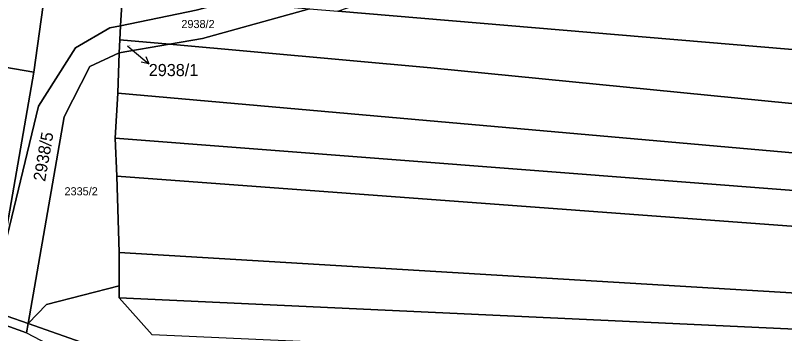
# Model space of a CAD drawing. Extents: x -596024 to -594475, y -1163820 to -1161957.
# Drawn here: x -595937.3 to -595829.3, y -1163270.2 to -1163225.5 of the extents above; entities that cross this region are included whole.
import ezdxf

# ---------------------------------------------------------------- set-up
doc = ezdxf.new("R2010")
doc.units = 0
for name, color, linetype in [('Level 1', 7, 'Continuous'), ('Level 3', 7, 'Continuous'), ('Level 4', 7, 'Continuous'), ('Level 57', 7, 'Continuous'), ('Level 60', 7, 'Continuous')]:
    doc.layers.add(name, color=color, linetype=linetype)

msp = doc.modelspace()

# ---------------------------------------------------------------- linework, layer by layer
at = {"layer": 'Level 1'}
for points in [[(-595675.06, -1163215.07), (-595742.82, -1163230.33), (-595776.16, -1163236.05), (-595801.34, -1163238.84), (-595828.3, -1163237.91), (-595878.95, -1163232.89), (-595915.65, -1163229.59)], [(-595932.62, -1163218.69), (-595934.67, -1163233.53)], [(-595922.49, -1163226.99), (-595922.2, -1163222.4)], [(-595922.49, -1163226.99), (-595911.9, -1163224.8), (-595907.4, -1163223.65)], [(-595895.98, -1163224.61), (-595911, -1163228.8), (-595915.65, -1163229.59)], [(-595891.99, -1163224.95), (-595828.78, -1163230.26), (-595802.13, -1163230.39), (-595778.15, -1163228.18)], [(-595922.49, -1163226.99), (-595924, -1163227.3), (-595928.8, -1163230.1), (-595934, -1163238.3), (-595939.33, -1163260.4)], [(-595922.61, -1163228.97), (-595922.49, -1163226.99)], [(-595922.61, -1163228.97), (-595922.7, -1163230.8)], [(-595922.61, -1163228.97), (-595915.65, -1163229.59)], [(-595915.65, -1163229.59), (-595922.7, -1163230.8)], [(-595922.7, -1163230.8), (-595926.8, -1163232.7), (-595930.4, -1163239.8), (-595935.47, -1163268.79)], [(-595922.7, -1163230.8), (-595922.87, -1163236.44)], [(-595934.67, -1163233.53), (-595938.74, -1163232.83)], [(-595923.01, -1163248.12), (-595826.47, -1163255.26), (-595799.73, -1163254.93), (-595774.4, -1163253.15), (-595741.25, -1163247.54), (-595665.63, -1163233.08)], [(-595939.33, -1163260.4), (-595934.67, -1163233.53)], [(-595922.87, -1163236.44), (-595923.26, -1163242.75)], [(-595922.87, -1163236.44), (-595879.57, -1163240.28), (-595827.65, -1163244.87), (-595800.36, -1163244.19), (-595775.52, -1163242.15), (-595749.33, -1163238.47)], [(-595661.36, -1163240.73), (-595740.36, -1163256.28), (-595773.23, -1163261.51), (-595825.25, -1163264.65), (-595922.67, -1163258.81)], [(-595923.26, -1163242.75), (-595923.01, -1163248.12)], [(-595747.69, -1163244.89), (-595774.6, -1163248.81), (-595799.67, -1163250.23), (-595826.81, -1163250.23), (-595923.26, -1163242.75)], [(-595922.67, -1163265.17), (-595824.85, -1163269.71), (-595772.83, -1163266.06), (-595739.93, -1163261.11), (-595695.6, -1163253.73), (-595659.73, -1163244.35)], [(-595923.01, -1163248.12), (-595922.67, -1163258.81)], [(-595922.67, -1163258.81), (-595922.67, -1163263.51)], [(-595935.47, -1163268.79), (-595938.42, -1163267.75), (-595940.3, -1163265.98), (-595939.33, -1163260.4)], [(-595935.47, -1163268.79), (-595932.89, -1163266.12), (-595922.67, -1163263.51)], [(-595922.67, -1163263.51), (-595922.67, -1163265.17)], [(-595918.05, -1163270.37), (-595922.67, -1163265.17)], [(-595941.6, -1163268), (-595935.7, -1163270.1)], [(-595935.47, -1163268.79), (-595935.7, -1163270.1)], [(-595888.83, -1163297.12), (-595911.69, -1163279.96), (-595927.25, -1163271.68), (-595935.47, -1163268.79)]]:
    msp.add_lwpolyline(points, dxfattribs=at)
at = {"layer": 'Level 3'}
msp.add_lwpolyline([(-595935.7, -1163270.1), (-595913.2, -1163281.9), (-595901.37, -1163289.13), (-595889.6, -1163298.16)], dxfattribs=at)
at = {"layer": 'Level 57'}
for p, q in [((-595921.5, -1163229.82), (-595920.82, -1163230.41)), ((-595920.82, -1163230.41), (-595918.54, -1163232.36))]:
    msp.add_line(p, q, dxfattribs=at)
msp.add_lwpolyline([(-595918.97, -1163231.33), (-595918.54, -1163232.36), (-595919.62, -1163232.09)], dxfattribs=at)
at = {"layer": 'Level 60'}
for points in [[(-595938.74, -1163232.83), (-595947.62, -1163231.36), (-595954.46, -1163230.21), (-595961.69, -1163228.79), (-595968.72, -1163227.41), (-595968.24, -1163224.95), (-595966.66, -1163216.91), (-595966.01, -1163213.62), (-595964.36, -1163205.23), (-595936.07, -1163208.09), (-595931.23, -1163208.58), (-595931.47, -1163210.3), (-595932.62, -1163218.69), (-595934.67, -1163233.53)], [(-595828.78, -1163230.26), (-595802.13, -1163230.39), (-595778.15, -1163228.18), (-595776.87, -1163228.06), (-595742.94, -1163222.14), (-595678.46, -1163208.15), (-595675.06, -1163215.07), (-595742.82, -1163230.33), (-595776.16, -1163236.05), (-595801.34, -1163238.84), (-595828.3, -1163237.91), (-595878.95, -1163232.89), (-595915.65, -1163229.59), (-595911, -1163228.8), (-595895.98, -1163224.61), (-595891.99, -1163224.95)], [(-595742.82, -1163230.33), (-595675.06, -1163215.07), (-595671.73, -1163222.03), (-595742.2, -1163237.47), (-595749.33, -1163238.47), (-595775.52, -1163242.15), (-595800.36, -1163244.19), (-595827.65, -1163244.87), (-595879.57, -1163240.28), (-595922.87, -1163236.44), (-595922.7, -1163230.8), (-595915.65, -1163229.59), (-595878.95, -1163232.89), (-595828.3, -1163237.91), (-595801.34, -1163238.84), (-595776.16, -1163236.05)], [(-595802.13, -1163230.39), (-595828.78, -1163230.26), (-595891.99, -1163224.95), (-595875.92, -1163219.36), (-595829.67, -1163222.92), (-595802.74, -1163224.11), (-595779.31, -1163221.24), (-595778.15, -1163228.18)], [(-595911.9, -1163224.8), (-595922.49, -1163226.99), (-595922.2, -1163222.4), (-595907.4, -1163223.65)], [(-595895.98, -1163224.61), (-595911, -1163228.8), (-595915.65, -1163229.59), (-595922.61, -1163228.97), (-595922.49, -1163226.99), (-595911.9, -1163224.8), (-595907.4, -1163223.65)], [(-595922.7, -1163230.8), (-595926.8, -1163232.7), (-595930.4, -1163239.8), (-595935.47, -1163268.79), (-595938.42, -1163267.75), (-595940.3, -1163265.98), (-595939.33, -1163260.4), (-595934, -1163238.3), (-595928.8, -1163230.1), (-595924, -1163227.3), (-595922.49, -1163226.99), (-595922.61, -1163228.97)], [(-595741.65, -1163244.01), (-595667.91, -1163228.35), (-595665.63, -1163233.08), (-595741.25, -1163247.54), (-595774.4, -1163253.15), (-595799.73, -1163254.93), (-595826.47, -1163255.26), (-595923.01, -1163248.12), (-595923.26, -1163242.75), (-595826.81, -1163250.23), (-595799.67, -1163250.23), (-595774.6, -1163248.81), (-595747.69, -1163244.89)], [(-595915.65, -1163229.59), (-595922.7, -1163230.8), (-595922.61, -1163228.97)], [(-595922.87, -1163236.44), (-595923.26, -1163242.75), (-595923.01, -1163248.12), (-595922.67, -1163258.81), (-595922.67, -1163263.51), (-595932.89, -1163266.12), (-595935.47, -1163268.79), (-595930.4, -1163239.8), (-595926.8, -1163232.7), (-595922.7, -1163230.8)], [(-595826.47, -1163255.26), (-595799.73, -1163254.93), (-595774.4, -1163253.15), (-595741.25, -1163247.54), (-595665.63, -1163233.08), (-595661.36, -1163240.73), (-595740.36, -1163256.28), (-595773.23, -1163261.51), (-595825.25, -1163264.65), (-595922.67, -1163258.81), (-595923.01, -1163248.12)], [(-595827.65, -1163244.87), (-595800.36, -1163244.19), (-595775.52, -1163242.15), (-595749.33, -1163238.47), (-595747.69, -1163244.89), (-595774.6, -1163248.81), (-595799.67, -1163250.23), (-595826.81, -1163250.23), (-595923.26, -1163242.75), (-595922.87, -1163236.44), (-595879.57, -1163240.28)], [(-595740.36, -1163256.28), (-595661.36, -1163240.73), (-595659.73, -1163244.35), (-595695.6, -1163253.73), (-595739.93, -1163261.11), (-595772.83, -1163266.06), (-595824.85, -1163269.71), (-595922.67, -1163265.17), (-595922.67, -1163263.51), (-595922.67, -1163258.81), (-595825.25, -1163264.65), (-595773.23, -1163261.51)], [(-595824.85, -1163269.71), (-595772.83, -1163266.06), (-595739.93, -1163261.11), (-595695.6, -1163253.73), (-595659.73, -1163244.35), (-595658.54, -1163248.02), (-595695.09, -1163258.13), (-595739.48, -1163265.3), (-595772.41, -1163270.66), (-595777.58, -1163271.05), (-595824.57, -1163274.61), (-595918.05, -1163270.37), (-595922.67, -1163265.17)], [(-595941.6, -1163268), (-595940.9, -1163266.9), (-595939.33, -1163260.4), (-595940.3, -1163265.98), (-595938.42, -1163267.75), (-595935.47, -1163268.79), (-595935.7, -1163270.1)]]:
    msp.add_lwpolyline(points, close=True, dxfattribs=at)
for points in [[(-595922.2, -1163222.4), (-595922.49, -1163226.99), (-595924, -1163227.3), (-595928.8, -1163230.1), (-595934, -1163238.3), (-595939.33, -1163260.4), (-595934.67, -1163233.53), (-595932.62, -1163218.69)], [(-595938.74, -1163232.83), (-595934.67, -1163233.53), (-595939.33, -1163260.4)], [(-595927.25, -1163271.68), (-595935.47, -1163268.79), (-595932.89, -1163266.12), (-595922.67, -1163263.51), (-595922.67, -1163265.17), (-595918.05, -1163270.37)], [(-595941.6, -1163268), (-595935.7, -1163270.1), (-595935.47, -1163268.79), (-595927.25, -1163271.68), (-595911.69, -1163279.96), (-595888.83, -1163297.12), (-595889.6, -1163298.16), (-595893, -1163302.7), (-595899.7, -1163298.5), (-595903.18, -1163297.24), (-595921.94, -1163285.18), (-595930.57, -1163281.25), (-595933.98, -1163279.7), (-595935.7, -1163279.3), (-595945.61, -1163275.5)]]:
    msp.add_lwpolyline(points, dxfattribs=at)

# ---------------------------------------------------------------- texts
at = {"layer": 'Level 4'}
for s, height, p in [('2938/2', 1.14, (-595913.96, -1163227.32)), ('2938/1', 0.1, (-595921.5, -1163229.82)), ('2335/2', 1.14, (-595930.36, -1163250.8))]:
    msp.add_text(s, height=height, dxfattribs=at).set_placement(p)
msp.add_text('2938/5', height=1.7, rotation=80.08, dxfattribs=at).set_placement((-595933.09, -1163248.93))
at = {"layer": 'Level 57'}
msp.add_text('2938/1', height=1.7, dxfattribs=at).set_placement((-595918.54, -1163234.06))

doc.saveas('drawing.dxf')
